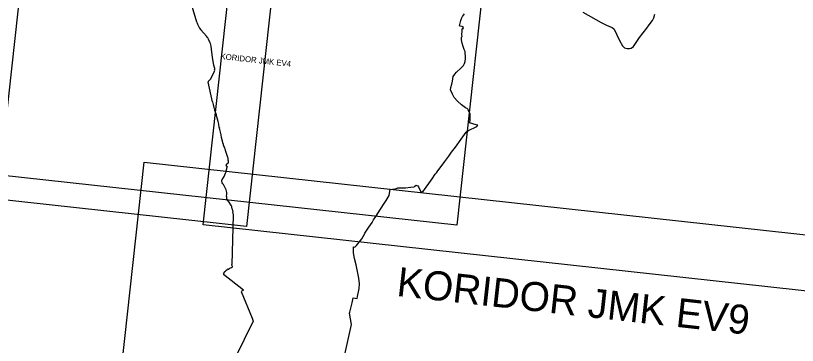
# Model space of a CAD drawing. Extents: x -678204 to -526855, y -1228851 to -1110393.
# Drawn here: x -600114 to -592047, y -1161054 to -1157650 of the extents above; entities that cross this region are included whole.
import ezdxf

# ---------------------------------------------------------------- set-up
doc = ezdxf.new("R2010")
doc.units = 0
for name, color, linetype in [('00_n_cyklo popisy', 7, 'Continuous'), ('00_n_cyklo popisy detaily', 7, 'Continuous'), ('00_n_cyklo prujezdne rekreacni hlavni', 7, 'Continuous'), ('00_n_cyklo studie rekreacni hlavni', 7, 'Continuous'), ('00_n_cyklo trasovani rekreacni hlavni', 7, 'Continuous'), ('_HELP', 7, 'Continuous'), ('_HELP BIG', 7, 'Continuous')]:
    doc.layers.add(name, color=color, linetype=linetype)

msp = doc.modelspace()

# ---------------------------------------------------------------- linework, layer by layer
at = {"layer": '00_n_cyklo prujezdne rekreacni hlavni'}
for points in [[(-594261.8, -1157612.6), (-594071.2, -1157719.5), (-594015.7, -1157747.9), (-593959.8, -1157774.1), (-593941.8, -1157787), (-593937.8, -1157789.9), (-593883.5, -1157906.2), (-593850.4, -1157960.5), (-593831.5, -1157982), (-593804.5, -1157989.6), (-593778.8, -1157989.2), (-593761, -1157985.2), (-593736.7, -1157967.2), (-593682.1, -1157887), (-593675.3, -1157874.6), (-593600.9, -1157777.9), (-593576.6, -1157744), (-593540.8, -1157701.8), (-593528.6, -1157673.7), (-593516.7, -1157635.1)], [(-596758.1, -1161334.5), (-596649.3, -1160836.8), (-596667.9, -1160721.6), (-596665.2, -1160710.5), (-596641.6, -1160613), (-596631.7, -1160562.2), (-596590.2, -1160570.8), (-596585.7, -1160548.3), (-596569.2, -1160466.6), (-596566.9, -1160418), (-596571.5, -1160360.2), (-596599.8, -1160220.7), (-596618.8, -1160156.5), (-596626.8, -1160097.5), (-596627.1, -1160036.5), (-596613.3, -1160039.4), (-596595.8, -1160023.8), (-596542.7, -1159952.7), (-596514.9, -1159905.9), (-596509.1, -1159894.7), (-596468.5, -1159833.8), (-596436.3, -1159785.2), (-596419.6, -1159757.5), (-596396.3, -1159722.4), (-596373, -1159685.4), (-596316.4, -1159599.1), (-596290.8, -1159557.5), (-596258.9, -1159507.3), (-596254.5, -1159484.1), (-596250.2, -1159444.1), (-596223.5, -1159441), (-596199.4, -1159439.1), (-596184.2, -1159434.5), (-596171.2, -1159429.2), (-596150.6, -1159426.5), (-596132.7, -1159427.3), (-596092.1, -1159429.2), (-596038.6, -1159422.3), (-596002.4, -1159418.5), (-595993.2, -1159411.6), (-595982.5, -1159398.5), (-595962.7, -1159408.4), (-595958.2, -1159417.4), (-595932.6, -1159468.3), (-595929, -1159478.9), (-595916.5, -1159465.9), (-595910.6, -1159470.2), (-595817.1, -1159333.8), (-595783.2, -1159285.7), (-595769.4, -1159272.9), (-595763.5, -1159263.2), (-595685.8, -1159157.1), (-595645.1, -1159100.9), (-595623.2, -1159069.7), (-595615.4, -1159060.5), (-595576.3, -1159008.4), (-595516.9, -1158924.6), (-595463.8, -1158852.6), (-595457, -1158847.2), (-595442.4, -1158837), (-595354.2, -1158794.1), (-595344, -1158779.5), (-595362.5, -1158776.1), (-595431.4, -1158755), (-595424.2, -1158733.9), (-595423.6, -1158695.9), (-595423.1, -1158667.1), (-595432.4, -1158639.5), (-595444.2, -1158623.3), (-595448.5, -1158614.9), (-595456.2, -1158610), (-595463.4, -1158605.3), (-595473, -1158600.3), (-595514.1, -1158569.5), (-595554.4, -1158534.4), (-595589.5, -1158495), (-595606.8, -1158459.4), (-595625.4, -1158415.4), (-595624.1, -1158391.6), (-595613.3, -1158358.7), (-595606.5, -1158326.1), (-595597.5, -1158276.8), (-595582.1, -1158252.6), (-595564.6, -1158233.3), (-595520.4, -1158193.9), (-595492.6, -1158166.1), (-595482.5, -1158145.8), (-595475.9, -1158122.5), (-595471.1, -1158093.8), (-595471.1, -1158066.9), (-595474.1, -1158037.7), (-595475.9, -1158018.6), (-595484.3, -1157998.9), (-595495.3, -1157969), (-595504.8, -1157933.6), (-595511.5, -1157900.7), (-595513.9, -1157878.2), (-595514.2, -1157873), (-595511.1, -1157867.7), (-595506.4, -1157867.1), (-595508.2, -1157846), (-595506.7, -1157809), (-595505.7, -1157795.6), (-595504.8, -1157787.9), (-595504, -1157784.1), (-595500.8, -1157782.4), (-595493.8, -1157781.4), (-595495.5, -1157773.3), (-595495.2, -1157766.6), (-595507.7, -1157763.1), (-595527.1, -1157757.7), (-595532.7, -1157756.1), (-595520.1, -1157701.3), (-595513.9, -1157679.2), (-595503, -1157657.7), (-595481.9, -1157631.1)], [(-597762.7, -1160485.5), (-597788, -1160499.2), (-597672.3, -1160771.7), (-597664.4, -1160803.1), (-597848.3, -1161181.6), (-597873.2, -1161200.9), (-598175.6, -1161332.6), (-598240.4, -1161398.9), (-598706.3, -1161903.9)]]:
    msp.add_lwpolyline(points, dxfattribs=at)
at = {"layer": '00_n_cyklo studie rekreacni hlavni'}
for p, q in [((-598245.5, -1157716.1), (-598349.5, -1157356.6)), ((-598146, -1157861.2), (-598201.4, -1157797.2)), ((-598114.2, -1157912.1), (-598118.9, -1157902.4)), ((-598101, -1158302.8), (-598062.1, -1158221.6)), ((-598082.8, -1158540), (-598127.3, -1158336.3)), ((-598125.6, -1158330.6), (-598111.8, -1158317.6)), ((-598012.5, -1158803.1), (-598018.2, -1158769.6)), ((-597993.7, -1158878.9), (-598010.9, -1158810.9)), ((-597924.2, -1159113.1), (-597947.5, -1159041.4)), ((-597928.9, -1159213.2), (-597941.1, -1159192.3)), ((-597939.6, -1159184.5), (-597921.5, -1159170.9)), ((-597931.6, -1159214.7), (-597928.9, -1159213.2)), ((-597938.5, -1159518.4), (-597935.9, -1159490.8)), ((-597881, -1160217.2), (-597866.5, -1159710.5)), ((-597920.4, -1160266.9), (-597915.3, -1160267.2)), ((-597877.3, -1160241), (-597884.5, -1160225.7)), ((-597969, -1160313.5), (-597950.5, -1160290.1)), ((-597762.7, -1160485.5), (-597968, -1160322))]:
    msp.add_line(p, q, dxfattribs=at)
for points in [[(-598081, -1158078.2), (-598088.5, -1158026.8), (-598097.5, -1157966.1)], [(-598068.6, -1158163.5), (-598081, -1158078.2)], [(-597973.9, -1158973.6), (-597990.8, -1158908.4), (-597993.7, -1158878.9)], [(-597921.6, -1159144.5), (-597921.7, -1159144), (-597921.9, -1159140.2), (-597921.9, -1159138.3), (-597921.9, -1159135.9), (-597921.8, -1159132.4)], [(-597917.8, -1159156), (-597919.8, -1159151.5)], [(-597917.9, -1159164.8), (-597917.3, -1159159.2)], [(-597947.4, -1159276.8), (-597942.6, -1159260.9)], [(-597983.8, -1159345.1), (-597982, -1159342.8)], [(-597975.7, -1159386.1), (-597983.5, -1159376.4)], [(-597947.8, -1159433.2), (-597965.4, -1159401.2)], [(-597892.3, -1159602.7), (-597911, -1159575), (-597927.5, -1159554.6)], [(-597880, -1159647.6), (-597884.5, -1159622)], [(-597866.8, -1159707.4), (-597874.3, -1159675.9)], [(-597943.3, -1160279.6), (-597930.4, -1160269.9)], [(-597907.3, -1160260.1), (-597903.5, -1160257.9), (-597896, -1160254.2), (-597886.2, -1160249.3), (-597884.4, -1160248.3), (-597882.7, -1160247.3), (-597878.5, -1160244.9)]]:
    msp.add_lwpolyline(points, dxfattribs=at)
for centre, radius, start, end in [((-598038.7, -1157656.3), 215.2, 196.13033, 220.89569), ((-598287.9, -1157984.1), 187.8, 25.81215, 40.89569), ((-598283.2, -1157993.9), 187.8, 8.49194, 25.81215), ((-597769.5, -1158120), 302.2, 188.27821, 195.73448), ((-598087.4, -1158209.5), 28, 334.40968, 15.73448), ((-598121.5, -1158335), 6, 133.28387, 192.32807), ((-598146.1, -1158281.2), 50, 313.28387, 334.40968), ((-597066.1, -1158320), 1040.3, 192.20953, 198.6947), ((-597581.4, -1158494.4), 496.2, 198.6947, 200.61296), ((-598575.8, -1158868.5), 566.3, 10.05472, 20.61296), ((-597914, -1158786.3), 100, 189.66101, 194.22668), ((-597778.8, -1158923.2), 201.5, 194.48805, 206.61258), ((-598139.1, -1159103.7), 201.5, 18.00889, 26.61258), ((-597973.1, -1159129), 51.5, 356.17322, 18.00889), ((-597900.2, -1159142.6), 21.5, 184.95027, 204.49063), ((-597923.2, -1159158.5), 6, 353.231, 24.49063), ((-598133.9, -1159202.8), 200, 343.09459, 355.21434), ((-597935.9, -1159189.3), 6, 126.89002, 210.33889), ((-597928.7, -1159220), 6, 119.3178, 175.21434), ((-597926.9, -1159163.7), 9, 306.89002, 353.231), ((-598138.8, -1159218.6), 200, 321.62616, 343.09459), ((-597964.2, -1159360.6), 25, 141.62616, 219.31274), ((-598053, -1159449.4), 100, 28.82713, 39.31274), ((-598035.4, -1159481.4), 100, 354.60362, 28.82713), ((-597888.7, -1159523.1), 50, 174.60362, 219.00564), ((-597933.8, -1159630.7), 50, 9.91776, 34.0018), ((-597387.5, -1159561.5), 500, 189.91776, 193.23044), ((-597878.5, -1159710.2), 12, 358.36411, 13.23044), ((-597962.3, -1160280.8), 15, 321.69312, 339.09707), ((-597934.2, -1160291.6), 15, 126.91983, 159.09707), ((-597921.4, -1160281.9), 15, 86.50708, 126.91983), ((-597915.1, -1160264.2), 3, 266.50708, 333.62976), ((-597900.8, -1160271.3), 13, 120.18436, 153.62976), ((-597881.8, -1160224.4), 3, 125.19508, 205.37771), ((-597887, -1160217.1), 6, 305.19508, 358.36411), ((-597880, -1160242.3), 3, 299.46196, 25.37771), ((-597964.3, -1160317.3), 6, 141.69312, 231.46252)]:
    msp.add_arc(centre, radius, start, end, dxfattribs=at)
at = {"layer": '00_n_cyklo trasovani rekreacni hlavni'}
for p, q in [((-598245.5, -1157716.1), (-598349.5, -1157356.6)), ((-598146, -1157861.2), (-598201.4, -1157797.2)), ((-598114.2, -1157912.1), (-598118.9, -1157902.4)), ((-598101, -1158302.8), (-598062.1, -1158221.6)), ((-598082.8, -1158540), (-598127.3, -1158336.3)), ((-598125.6, -1158330.6), (-598111.8, -1158317.6)), ((-598012.5, -1158803.1), (-598018.2, -1158769.6)), ((-597993.7, -1158878.9), (-598010.9, -1158810.9)), ((-597924.2, -1159113.1), (-597947.5, -1159041.4)), ((-597928.9, -1159213.2), (-597941.1, -1159192.3)), ((-597939.6, -1159184.5), (-597921.5, -1159170.9)), ((-597931.6, -1159214.7), (-597928.9, -1159213.2)), ((-597938.5, -1159518.4), (-597935.9, -1159490.8)), ((-597881, -1160217.2), (-597866.5, -1159710.5)), ((-597920.4, -1160266.9), (-597915.3, -1160267.2)), ((-597877.3, -1160241), (-597884.5, -1160225.7)), ((-597969, -1160313.5), (-597950.5, -1160290.1)), ((-597762.7, -1160485.5), (-597968, -1160322))]:
    msp.add_line(p, q, dxfattribs=at)
for points in [[(-594261.8, -1157612.6), (-594071.2, -1157719.5), (-594015.7, -1157747.9), (-593959.8, -1157774.1), (-593941.8, -1157787), (-593937.8, -1157789.9), (-593883.5, -1157906.2), (-593850.4, -1157960.5), (-593831.5, -1157982), (-593804.5, -1157989.6), (-593778.8, -1157989.2), (-593761, -1157985.2), (-593736.7, -1157967.2), (-593682.1, -1157887), (-593675.3, -1157874.6), (-593600.9, -1157777.9), (-593576.6, -1157744), (-593540.8, -1157701.8), (-593528.6, -1157673.7), (-593516.7, -1157635.1)], [(-596758.1, -1161334.5), (-596649.3, -1160836.8), (-596667.9, -1160721.6), (-596665.2, -1160710.5), (-596641.6, -1160613), (-596631.7, -1160562.2), (-596590.2, -1160570.8), (-596585.7, -1160548.3), (-596569.2, -1160466.6), (-596566.9, -1160418), (-596571.5, -1160360.2), (-596599.8, -1160220.7), (-596618.8, -1160156.5), (-596626.8, -1160097.5), (-596627.1, -1160036.5), (-596613.3, -1160039.4), (-596595.8, -1160023.8), (-596542.7, -1159952.7), (-596514.9, -1159905.9), (-596509.1, -1159894.7), (-596468.5, -1159833.8), (-596436.3, -1159785.2), (-596419.6, -1159757.5), (-596396.3, -1159722.4), (-596373, -1159685.4), (-596316.4, -1159599.1), (-596290.8, -1159557.5), (-596258.9, -1159507.3), (-596254.5, -1159484.1), (-596250.2, -1159444.1), (-596223.5, -1159441), (-596199.4, -1159439.1), (-596184.2, -1159434.5), (-596171.2, -1159429.2), (-596150.6, -1159426.5), (-596132.7, -1159427.3), (-596092.1, -1159429.2), (-596038.6, -1159422.3), (-596002.4, -1159418.5), (-595993.2, -1159411.6), (-595982.5, -1159398.5), (-595962.7, -1159408.4), (-595958.2, -1159417.4), (-595932.6, -1159468.3), (-595929, -1159478.9), (-595916.5, -1159465.9), (-595910.6, -1159470.2), (-595817.1, -1159333.8), (-595783.2, -1159285.7), (-595769.4, -1159272.9), (-595763.5, -1159263.2), (-595685.8, -1159157.1), (-595645.1, -1159100.9), (-595623.2, -1159069.7), (-595615.4, -1159060.5), (-595576.3, -1159008.4), (-595516.9, -1158924.6), (-595463.8, -1158852.6), (-595457, -1158847.2), (-595442.4, -1158837), (-595354.2, -1158794.1), (-595344, -1158779.5), (-595362.5, -1158776.1), (-595431.4, -1158755), (-595424.2, -1158733.9), (-595423.6, -1158695.9), (-595423.1, -1158667.1), (-595432.4, -1158639.5), (-595444.2, -1158623.3), (-595448.5, -1158614.9), (-595456.2, -1158610), (-595463.4, -1158605.3), (-595473, -1158600.3), (-595514.1, -1158569.5), (-595554.4, -1158534.4), (-595589.5, -1158495), (-595606.8, -1158459.4), (-595625.4, -1158415.4), (-595624.1, -1158391.6), (-595613.3, -1158358.7), (-595606.5, -1158326.1), (-595597.5, -1158276.8), (-595582.1, -1158252.6), (-595564.6, -1158233.3), (-595520.4, -1158193.9), (-595492.6, -1158166.1), (-595482.5, -1158145.8), (-595475.9, -1158122.5), (-595471.1, -1158093.8), (-595471.1, -1158066.9), (-595474.1, -1158037.7), (-595475.9, -1158018.6), (-595484.3, -1157998.9), (-595495.3, -1157969), (-595504.8, -1157933.6), (-595511.5, -1157900.7), (-595513.9, -1157878.2), (-595514.2, -1157873), (-595511.1, -1157867.7), (-595506.4, -1157867.1), (-595508.2, -1157846), (-595506.7, -1157809), (-595505.7, -1157795.6), (-595504.8, -1157787.9), (-595504, -1157784.1), (-595500.8, -1157782.4), (-595493.8, -1157781.4), (-595495.5, -1157773.3), (-595495.2, -1157766.6), (-595507.7, -1157763.1), (-595527.1, -1157757.7), (-595532.7, -1157756.1), (-595520.1, -1157701.3), (-595513.9, -1157679.2), (-595503, -1157657.7), (-595481.9, -1157631.1)], [(-598081, -1158078.2), (-598088.5, -1158026.8), (-598097.5, -1157966.1)], [(-598068.6, -1158163.5), (-598081, -1158078.2)], [(-597973.9, -1158973.6), (-597990.8, -1158908.4), (-597993.7, -1158878.9)], [(-597921.6, -1159144.5), (-597921.7, -1159144), (-597921.9, -1159140.2), (-597921.9, -1159138.3), (-597921.9, -1159135.9), (-597921.8, -1159132.4)], [(-597917.8, -1159156), (-597919.8, -1159151.5)], [(-597917.9, -1159164.8), (-597917.3, -1159159.2)], [(-597947.4, -1159276.8), (-597942.6, -1159260.9)], [(-597983.8, -1159345.1), (-597982, -1159342.8)], [(-597975.7, -1159386.1), (-597983.5, -1159376.4)], [(-597947.8, -1159433.2), (-597965.4, -1159401.2)], [(-597892.3, -1159602.7), (-597911, -1159575), (-597927.5, -1159554.6)], [(-597880, -1159647.6), (-597884.5, -1159622)], [(-597866.8, -1159707.4), (-597874.3, -1159675.9)], [(-597943.3, -1160279.6), (-597930.4, -1160269.9)], [(-597907.3, -1160260.1), (-597903.5, -1160257.9), (-597896, -1160254.2), (-597886.2, -1160249.3), (-597884.4, -1160248.3), (-597882.7, -1160247.3), (-597878.5, -1160244.9)], [(-597762.7, -1160485.5), (-597788, -1160499.2), (-597672.3, -1160771.7), (-597664.4, -1160803.1), (-597848.3, -1161181.6), (-597873.2, -1161200.9), (-598175.6, -1161332.6), (-598240.4, -1161398.9), (-598706.3, -1161903.9)]]:
    msp.add_lwpolyline(points, dxfattribs=at)
for centre, radius, start, end in [((-598038.7, -1157656.3), 215.2, 196.13033, 220.89569), ((-598287.9, -1157984.1), 187.8, 25.81215, 40.89569), ((-598283.2, -1157993.9), 187.8, 8.49194, 25.81215), ((-597769.5, -1158120), 302.2, 188.27821, 195.73448), ((-598087.4, -1158209.5), 28, 334.40968, 15.73448), ((-598121.5, -1158335), 6, 133.28387, 192.32807), ((-598146.1, -1158281.2), 50, 313.28387, 334.40968), ((-597066.1, -1158320), 1040.3, 192.20953, 198.6947), ((-597581.4, -1158494.4), 496.2, 198.6947, 200.61296), ((-598575.8, -1158868.5), 566.3, 10.05472, 20.61296), ((-597914, -1158786.3), 100, 189.66101, 194.22668), ((-597778.8, -1158923.2), 201.5, 194.48805, 206.61258), ((-598139.1, -1159103.7), 201.5, 18.00889, 26.61258), ((-597973.1, -1159129), 51.5, 356.17322, 18.00889), ((-597900.2, -1159142.6), 21.5, 184.95027, 204.49063), ((-597923.2, -1159158.5), 6, 353.231, 24.49063), ((-598133.9, -1159202.8), 200, 343.09459, 355.21434), ((-597935.9, -1159189.3), 6, 126.89002, 210.33889), ((-597928.7, -1159220), 6, 119.3178, 175.21434), ((-597926.9, -1159163.7), 9, 306.89002, 353.231), ((-598138.8, -1159218.6), 200, 321.62616, 343.09459), ((-597964.2, -1159360.6), 25, 141.62616, 219.31274), ((-598053, -1159449.4), 100, 28.82713, 39.31274), ((-598035.4, -1159481.4), 100, 354.60362, 28.82713), ((-597888.7, -1159523.1), 50, 174.60362, 219.00564), ((-597933.8, -1159630.7), 50, 9.91776, 34.0018), ((-597387.5, -1159561.5), 500, 189.91776, 193.23044), ((-597878.5, -1159710.2), 12, 358.36411, 13.23044), ((-597962.3, -1160280.8), 15, 321.69312, 339.09707), ((-597934.2, -1160291.6), 15, 126.91983, 159.09707), ((-597921.4, -1160281.9), 15, 86.50708, 126.91983), ((-597915.1, -1160264.2), 3, 266.50708, 333.62976), ((-597900.8, -1160271.3), 13, 120.18436, 153.62976), ((-597881.8, -1160224.4), 3, 125.19508, 205.37771), ((-597887, -1160217.1), 6, 305.19508, 358.36411), ((-597880, -1160242.3), 3, 299.46196, 25.37771), ((-597964.3, -1160317.3), 6, 141.69312, 231.46252)]:
    msp.add_arc(centre, radius, start, end, dxfattribs=at)
at = {"layer": '_HELP'}
msp.add_lwpolyline([(-599907, -1155939.4), (-595192.5, -1156457.1), (-595561.2, -1159814.6), (-600275.7, -1159296.9)], close=True, dxfattribs=at)
at = {"layer": '_HELP BIG'}
for points in [[(-617877.4, -1157614.7), (-614771.3, -1129327.4), (-594626.3, -1131539.4), (-597732.4, -1159826.8)], [(-598180, -1159809.1), (-595073.9, -1131521.8), (-574928.9, -1133733.9), (-578035.1, -1162021.2)], [(-572713.2, -1182415), (-601000.5, -1179308.8), (-598788.5, -1159163.8), (-570501.1, -1162270)]]:
    msp.add_lwpolyline(points, close=True, dxfattribs=at)

# ---------------------------------------------------------------- texts
at = {"layer": '00_n_cyklo popisy'}
msp.add_text('KORIDOR JMK EV9', height=300, rotation=353.68355, dxfattribs=at).set_placement((-596190.4, -1160542.1))
at = {"layer": '00_n_cyklo popisy detaily'}
msp.add_text('KORIDOR JMK EV4', height=60, rotation=353.68355, dxfattribs=at).set_placement((-598002.4, -1158098.2))

doc.saveas('drawing.dxf')
